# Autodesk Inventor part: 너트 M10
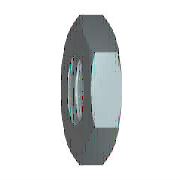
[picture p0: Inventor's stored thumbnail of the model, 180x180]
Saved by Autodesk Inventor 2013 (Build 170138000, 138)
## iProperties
IsCustomPart: 1
Created: 2012-02
Part Number: 너트 M10
Material: 강철, 연강
Description: 6각 가는 너트 - 이중 모따기
Document SubType Name: Modeling
Standard: JIS B 1181
Designer: mduedu
Standards Organization: JIS
Language: ko-KR
Size Designation: A/B M10
Categories: <MemberInstance><Categories><Category DisplayName="조임쇠" InternalName="e4da775c-781d-43d5-af7c-5136215cf5a6" Mnemonic="FSTN"><Category DisplayName="너트" InternalN
Density: 1 g/cm^3
Author: mduedu
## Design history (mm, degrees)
sketch "스케치1"
  geometry: L1 (-9.238, 0)-(-4.619, 8); L2 (-4.619, 8)-(4.619, 8); L3 (4.619, 8)-(9.238, 0); L4 (9.238, 0)-(4.619, -8); L5 (4.619, -8)-(-4.619, -8); L6 (-4.619, -8)-(-9.238, 0); 2 further points
  constraints: 12 end point, 1 coincident, 1 horizontal, 11 other
  dimensions: "d0" = 18.47521 distance of L3.end L1.start (= 1.1547 x SW)
extrude "본체" new body sketch "스케치1" distance "d1" = 5 (= KOH); taper "d2" = 0 deg
sketch "스케치2"
  geometry: L1 (0, 4.619)-(0, 9.238) reference; L2 (0, 9.238)-(5, 9.238) reference; L3 (5, 4.619)-(5, 9.238) reference; L4 (-1, 0)-(6, 0) reference; L5 (0.715, 9.238)-(0, 8); L6 (4.285, 9.238)-(5, 8)
  constraints: 4 end point, 4 point on line
  dimensions: "d3" = 30 deg angle of L1 L5 (= ANG1); "d4" = 30 deg angle of L3 L6 (= ANG2); "d5" = 16 diameter of L5.end L4 (= SW0); "d6" = 16 diameter of L6.end L4 (= SW01)
revolve "모따기1" sketch "스케치2" stored, may be unused: angle "d7" = 90 deg
sketch "스케치3"
  geometry: A1 r 8 centre (0, 0) between (-4, -6.928) and (4, -6.928) reference; 1 further point
  constraints: 1 coincident
hole "스레드" sketch "스케치3" at (0, 0) diameter "d25" = 8.376; stored, may be unused: countersink angle "d29" = 82 deg, drill point angle "d31" = 118 deg; dims "d26" = 6, "d27" = 4, "d28" = 2, "d30" = 8
workaxis "Work Axis1"
workplane "Work Plane1"
body "Solid1"
chamfer "모따기2" distance "d8" = 0.8119 (= -0.5 x GD1 + 0.5 x NND); stored, may be unused: angle "d9" = 30 deg, second distance "d40" = 0.8119 (= -0.5 x GD1 + 0.5 x NND)
chamfer "모따기3" distance "d10" = 0.8119 (= -0.5 x GD1 + 0.5 x NND); stored, may be unused: angle "d11" = 30 deg, second distance "d41" = 0.8119 (= -0.5 x GD1 + 0.5 x NND)
other parameters: "ANG1" = 30 deg [user parameter; used in 1 equation term], "ANG2" = 30 deg [user parameter; used in 1 equation term], "KOH" = 5 [user parameter; used in 1 equation term], "SW" = 16 [user parameter; used in 4 equation terms], "SW0" = 16 (= SW) [user parameter; used in 1 equation term], "SW01" = 16 (= SW) [user parameter; used in 1 equation term], "GD1" = 8.3762 (computed from THREADDIA, PTC, TOA) [user parameter; used in 4 equation terms], "d13" = 0, "d14" = 0, "d39" = 0, "d42" = 0, "GUL" = 0.8119 (= 0.541266 x PTC) [user parameter], "TPU" = 6.66667 (computed from PTC) [user parameter], "TOA" = 30 deg [user parameter; used in 1 equation term], "PTC" = 1.5 [user parameter; used in 4 equation terms], "E0" = 18.48 (= 1.155 x SW) [user parameter], "GAL" = 0.8119 (= 0.541266 x PTC) [user parameter]
